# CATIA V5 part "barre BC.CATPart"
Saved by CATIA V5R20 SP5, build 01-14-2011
Part number: barre BC
Bounding box of the stored display mesh (mm): x -10 to 0, y 91.655 to 213.016, z -9.902 to 182.199
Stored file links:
  F:\projet\yyang_IAO\barre BC.CATPart
  F:\projet\yyang_IAO\iao.CATProduct
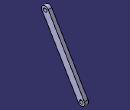
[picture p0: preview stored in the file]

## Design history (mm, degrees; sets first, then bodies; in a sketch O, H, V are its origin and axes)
External parameters (linked from other documents)
  `External.rayon de liaison` = 5 mm
  External.epaisseur = 10 mm
  External.Largeur = 20 mm
Set1
  Plane1: linked copy from another document
  Point1: linked copy from another document
  Point2: linked copy from another document
Body1 (main body)
  Sketch1 on Plane1, origin (0, 0, 0), H (0, 1, 0), V (0, 0, 1)
    circle A1 centre (203.1141, 0) radius 5
    point P1 (203.1141, 0)
    circle A2 centre (101.5571, 172.2967) radius 5
    point P2 (101.5571, 172.2967)
    reference projected point E1 (203.1141, 0) from Point1
    reference projected point E2 (203.1141, 0) from Point1
    reference projected point E3 (101.5571, 172.2967) from Point2
    reference projected point E4 (101.5571, 172.2967) from Point2
    construction line L1 (101.5571, 172.2967) -> (203.1141, 0)
    point P3 (101.5571, 172.2967)
    point P4 (203.1141, 0)
    line L2 (110.1719, 177.3746) -> (211.7289, 5.0779)
    line L3 (194.4993, -5.0779) -> (92.9422, 167.2189)
    arc A3 centre (203.1141, 0) radius 10 from (211.7289, 5.0779) to (194.4993, -5.0779) cw
    arc A4 centre (101.5571, 172.2967) radius 10 from (92.9422, 167.2189) to (110.1719, 177.3746) cw
    reference projected point E5 (203.1141, 0) from Point1
    reference projected point E6 (101.5571, 172.2967) from Point2
    distance A1 E2 = 5 {= `External.rayon de liaison`}
    distance A2 E4 = 5 {= `External.rayon de liaison`}
    distance L1 L2 = 10 {= External.Largeur/2}
    coincidence: P1 E1, P2 E3, P4 E5, P3 E6
    tangency: A3 L2, A4 L2, A3 L3, A4 L3
  Pad1: profile Sketch1, direction (-1, 0, 0), length 10 {= External.epaisseur}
